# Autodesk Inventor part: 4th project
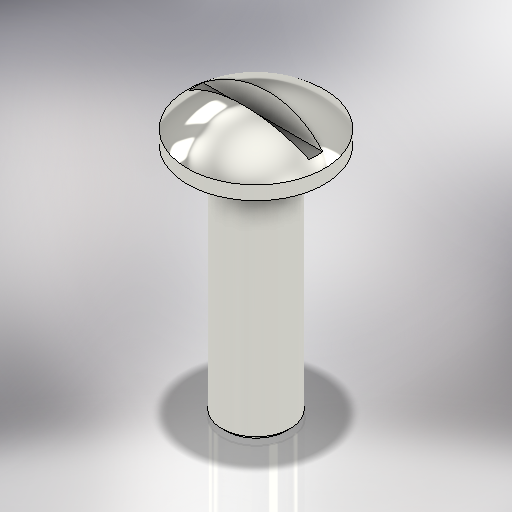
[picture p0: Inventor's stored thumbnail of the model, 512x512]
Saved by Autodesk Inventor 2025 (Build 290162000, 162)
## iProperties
Created: 2024-06
Part Number: 4th project
Material: Generic
Document SubType Name: Modeling
Designer: aryan
Density: 1 g/cm^3
Appearance: Silver
Author: aryan
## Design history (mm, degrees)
sketch "Sketch1"
  geometry: L1 (0, 0)-(0, 50.8); L2 (0, 0)-(-6.35, 0); L3 (-6.35, 0)-(-6.35, 43.18); L4 (-6.35, 43.18)-(-12.7, 43.18); L5 (-12.7, 43.18)-(-12.7, 45.72); A1 r 19.05 centre (0.253, 31.752) between (0, 50.8) and (-12.7, 45.72)
  constraints: 10 end point, 3 perpendicular, 2 point on circle, 1 centre point, 1 horizontal, 1 vertical
  dimensions: "d0" = 50.8 distance of L1.start L1.end; "d1" = 6.35 distance of L1.start L2.end; "d2" = 43.18 distance of L2.end L3.end; "d3" = 6.35 distance of L3.end L4.end; "d4" = 2.54 distance of L4.end L5.end; "d5" = 19.05 radius of A1
revolve "Revolution1" sketch "Sketch1" stored, may be unused: angle "d6" = 90 deg
sketch "Sketch2"
  geometry: L1 (0, 0)-(63.426, 0); L2 (54.496, 0)-(54.496, 3.281); L3 (54.496, 3.281)-(46.99, 1.27); L4 (46.99, 1.27)-(46.99, 0); L5 (54.496, -3.281)-(46.99, -1.27); L6 (54.496, 0)-(54.496, -3.281); L7 (46.99, -1.27)-(46.99, 0); L8 (43.18, -12.7)-(43.18, 12.7) reference
  constraints: 14 end point, 2 perpendicular, 2 point on line, 2 symmetric about line, 1 horizontal
  dimensions: "d7" = 3.81 distance between parallel lines of L8 L4; "d8" = 2.54 distance of L5.end L3.end; "d9" = 30 deg angle of L5 L3
extrude "Extrusion1" cut sketch "Sketch2" distance "d10" = 25.4; taper "d12" = 0 deg; dims "d11" = 12.7, "d13" = 0
chamfer "Chamfer1" distance "d14" = 0.762; stored, may be unused: second distance "d15" = 3.175, angle "d16" = 45 deg
body "Solid1"
